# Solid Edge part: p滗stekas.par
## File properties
Author: Andris
Template: Normal.par
Last saved by: Andris
Revision: 4
Application: Solid Edge
Accuracy: 0,990
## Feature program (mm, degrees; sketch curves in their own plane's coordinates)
make body feature "unnamed MakeBodyFeature 1"
thinwall "Thinwall_2"  Thickness = 1 mm
web network "WebNetwork_1"  Thickness = 0.25 mm
sketch for "ExtrudedProtrusion_1" plane through (4.9176, 0.3195, 4.5523) normal (0, 0, 1) x-axis (0, 1, 0)
  line (3.9894, 8.8745) -> (3.9894, 5.5143)
  line (3.9894, 5.5143) -> (-5.3159, 5.5143)
  line (-5.3159, 5.5143) -> (-5.3159, 8.8745)
  line (-5.3159, 8.8745) -> (3.9894, 8.8745)
extrude "ExtrudedProtrusion_1" add finite 2.5924 along +normal
sketch for "ExtrudedProtrusion_2" plane through (4.9176, 0.3195, 4.5523) normal (0, 0, 1) x-axis (0, 1, 0)
  line (-3.765, -4.308) -> (-8.5038, -4.308)
  line (-8.5038, -4.308) -> (-8.5038, -0.4308)
  line (-8.5038, -0.4308) -> (-3.765, -0.4308)
  line (-3.765, -0.4308) -> (-3.765, -4.308)
extrude "ExtrudedProtrusion_2" add finite 2.6405 along +normal
sketch for "ExtrudedProtrusion_3" plane through (4.9176, 0.3195, 4.5523) normal (0, 0, 1) x-axis (0, 1, 0)
  line (-8.7623, -12.9241) -> (7.2635, -12.9241)
  line (7.2635, -12.9241) -> (7.2635, -16.9736)
  line (7.2635, -16.9736) -> (-8.7623, -16.9736)
  line (-8.7623, -16.9736) -> (-8.7623, -12.9241)
extrude "ExtrudedProtrusion_3" add finite 5.2412 along +normal
sketch for "ExtrudedProtrusion_4" plane through (25.184, 0, 6.3726) normal (1, 0, 0) x-axis (0, 1, 0)
  line (8.898, 4.3942) -> (8.898, 2.058)
  line (8.898, 2.058) -> (8.5124, 2.058)
  line (8.5124, 2.058) -> (8.5124, 4.3942)
  line (8.5124, 4.3942) -> (8.898, 4.3942)
extrude "ExtrudedProtrusion_4" add finite 0.5 along +normal
sketch for "ExtrudedProtrusion_5" plane through (25.184, 0, 6.3726) normal (1, 0, 0) x-axis (0, 1, 0)
  line (6.2669, 2.9879) -> (7.1288, 2.0353)
  line (7.1288, 2.0353) -> (7.7866, 2.0353)
  line (7.7866, 2.0353) -> (6.834, 2.9879)
  bspline degree 3 poles (6.7432, 4.3942) (7.7103, 3.9406) (7.7405, 3.4718) (6.834, 2.9879) knots 0 1 multiplicities 4 4
  line (5.5638, 4.3942) -> (6.7432, 4.3942)
  line (5.5638, 4.3942) -> (5.5638, 2.0353)
  line (5.5638, 2.0353) -> (6.2669, 2.0353)
  line (6.2669, 2.0353) -> (6.2669, 2.9879)
extrude "ExtrudedProtrusion_5" add finite 0.5 along +normal
sketch for "ExtrudedProtrusion_7" plane through (25.184, 0, 6.3726) normal (1, 0, 0) x-axis (0, 1, 0)
  line (3.1863, 4.3205) -> (3.1863, 2.5044)
  line (3.1863, 4.3205) -> (2.5601, 4.3205)
  line (2.5601, 4.3205) -> (2.5601, 2.16)
  bspline degree 3 poles (4.7832, 2.16) (4.0838, 1.5934) (3.3428, 1.5934) (2.5601, 2.16) knots 0 1 multiplicities 4 4
  line (4.7832, 4.3205) -> (4.7832, 2.16)
  line (4.7832, 4.3205) -> (4.0944, 4.3205)
  line (4.0944, 4.3205) -> (4.0944, 2.5044)
  arc centre (4.0944, -14.1338) radius 16.6383 from (4.0944, 2.5044) to (3.1863, 2.4796) ccw
extrude "ExtrudedProtrusion_7" add finite 0.5 along +normal
sketch for "ExtrudedProtrusion_8" plane through (25.184, 0, 6.3726) normal (1, 0, 0) x-axis (0, 1, 0)
  line (-0.4881, 4.3205) -> (-0.4881, 2.5044)
  line (-0.4881, 4.3205) -> (-1.1144, 4.3205)
  line (-1.1144, 4.3205) -> (-1.1144, 2.16)
  bspline degree 3 poles (1.1088, 2.16) (0.4094, 1.5934) (-0.3317, 1.5934) (-1.1144, 2.16) knots 0 1 multiplicities 4 4
  line (1.1088, 4.3205) -> (1.1088, 2.16)
  line (1.1088, 4.3205) -> (0.4199, 4.3205)
  line (0.4199, 4.3205) -> (0.4199, 2.5044)
  arc centre (0.4199, -14.1338) radius 16.6383 from (0.4199, 2.5044) to (-0.4881, 2.4796) ccw
extrude "ExtrudedProtrusion_8" add finite 0.5 along +normal
sketch for "ExtrudedProtrusion_9" plane through (25.184, 0, 6.3726) normal (1, 0, 0) x-axis (0, 1, 0)
  line (-2.9192, 3.421) -> (-2.9192, 1.7858)
  line (-2.9192, 1.7858) -> (-3.6904, 1.7858)
  line (-3.6904, 1.7858) -> (-3.6904, 3.421)
  line (-3.6904, 3.421) -> (-4.8472, 3.421)
  line (-4.8472, 3.421) -> (-4.8245, 4.3205)
  line (-4.8245, 4.3205) -> (-1.9439, 4.3205)
  line (-1.9439, 4.3205) -> (-1.9439, 3.421)
  line (-1.9439, 3.421) -> (-2.9192, 3.421)
extrude "ExtrudedProtrusion_9" add finite 0.5 along +normal
sketch for "unnamed Protrusion 1" plane through (25.184, 0, 6.3726) normal (1, 0, 0) x-axis (0, 1, 0)
  line (-6.2575, 4.3205) -> (-6.2575, 2.5044)
  line (-6.2575, 4.3205) -> (-5.6313, 4.3205)
  line (-5.6313, 4.3205) -> (-5.6313, 2.16)
  bspline degree 3 poles (-7.8544, 2.16) (-7.155, 1.5934) (-6.414, 1.5934) (-5.6313, 2.16) knots 0 1 multiplicities 4 4
  line (-7.8544, 4.3205) -> (-7.8544, 2.16)
  line (-7.8544, 4.3205) -> (-7.1656, 4.3205)
  line (-7.1656, 4.3205) -> (-7.1656, 2.5044)
  arc centre (-7.1656, -14.1338) radius 16.6383 from (-7.1656, 2.5044) to (-6.2575, 2.4796) cw
extrude "unnamed Protrusion 1" add finite 0.5 along +normal
sketch for "ExtrudedProtrusion_11" plane through (25.184, 0, 6.3726) normal (1, 0, 0) x-axis (0, 1, 0)
  line (-8.8251, 3.1307) -> (-9.4545, 3.1307)
  line (-9.4545, 3.1307) -> (-9.4545, 3.7882)
  line (-9.4545, 3.7882) -> (-8.4428, 3.7882)
  line (-8.4428, 3.7882) -> (-8.4428, 4.3205)
  line (-8.4428, 4.3205) -> (-10.0776, 4.3205)
  line (-10.0776, 4.3205) -> (-10.0776, 1.9408)
  line (-10.0776, 1.9408) -> (-9.4545, 1.9408)
  line (-9.4545, 1.9408) -> (-9.4545, 2.5984)
  line (-9.4545, 2.5984) -> (-8.8251, 2.5984)
  line (-8.8251, 2.5984) -> (-8.8251, 3.1307)
extrude "ExtrudedProtrusion_11" add finite 0.5 along +normal
sketch for "ExtrudedProtrusion_12" plane through (-4.1931, 0, 0) normal (1, 0, 0) x-axis (0, 1, 0)
  line (16.7769, 11.2976) -> (16.7769, 0)
  line (16.7769, 0) -> (16.7769, -3.4038)
  line (16.7769, -3.4038) -> (-16.763, -3.4038)
  line (-16.763, -3.4038) -> (-16.763, 11.0814)
  line (-16.763, 11.0814) -> (-14.6275, 11.0814)
  bspline degree 3 poles (-14.6275, 11.0814) (-14.5757, 9.0634) (-14.3508, 5.8906) (-9.9977, 2.2169) (-5.2623, -0.108) (-1.6651, -0.5619) (0, -0.7388) knots 0 0.264 0.4468 0.7811 1 multiplicities 4 1 1 1 4
  bspline degree 3 poles (14.6275, 11.0814) (14.5757, 9.0634) (14.3508, 5.8906) (9.9977, 2.2169) (5.2623, -0.108) (1.6651, -0.5619) (0, -0.7388) knots 0 0.264 0.4468 0.7811 1 multiplicities 4 1 1 1 4
  line (14.6275, 11.0814) -> (14.4867, 11.2976)
  line (14.4867, 11.2976) -> (16.7769, 11.2976)
extrude "ExtrudedProtrusion_12" add finite 5 symmetric
mirror "unnamed Mirror 1" of "ExtrudedProtrusion_12" about plane through (4.3884, 0, 0) normal (1, 0, 0)
extrude "unnamed Protrusion 2" add finite 5 symmetric
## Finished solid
Body 1: solid body, 109 faces, 276 edges, 184 vertices, 3 separate solids.
  Faces by surface: plane 92, swept 8, offset 4, cylinder 3, spline 2
  Edges by curve: line 229, spline 17, intersection 16, curve on surface 8, circle 6
Body 2: solid body, 4 faces, 7 edges, 5 vertices.
  Faces by surface: plane 2, spline 2
  Edges by curve: curve on surface 6, spline 1
Bounding box of the edges (mm; curved faces can reach further): 45.439 x 33.540 x 16.149, from (-19.7553, -16.763, -3.4038) to (25.684, 16.7769, 12.7453).
Cylindrical faces by radius (mm): R16.6383 x3
Planar faces by outward normal: +x 14, +y 19, +z 21, -x 8, -y 15, -z 12, oblique 5
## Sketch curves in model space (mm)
line (-4.1931, 16.7769, 11.2976) -> (-4.1931, 16.7769, 0)
line (-4.1931, 16.7769, 0) -> (-4.1931, 16.7769, -3.4038)
line (-4.1931, 16.7769, -3.4038) -> (-4.1931, -16.763, -3.4038)
line (-4.1931, -16.763, -3.4038) -> (-4.1931, -16.763, 11.0814)
line (-4.1931, -16.763, 11.0814) -> (-4.1931, -14.6275, 11.0814)
spline (-4.1931, -14.6275, 11.0814) -> (-4.1931, -9.8346, 2.3914) -> (-4.1931, 0, -0.7388)
spline (-4.1931, 14.6275, 11.0814) -> (-4.1931, 9.8346, 2.3914) -> (-4.1931, 0, -0.7388)
line (-4.1931, 14.6275, 11.0814) -> (-4.1931, 14.4867, 11.2976)
line (-4.1931, 14.4867, 11.2976) -> (-4.1931, 16.7769, 11.2976)
line (25.184, -10.0776, 8.3134) -> (25.184, -9.4545, 8.3134)
line (25.184, -9.4545, 8.3134) -> (25.184, -9.4545, 8.971)
line (25.184, -9.4545, 8.971) -> (25.184, -8.8251, 8.971)
line (25.184, -8.8251, 8.971) -> (25.184, -8.8251, 9.5033)
line (25.184, -8.8251, 9.5033) -> (25.184, -9.4545, 9.5033)
line (25.184, -9.4545, 9.5033) -> (25.184, -9.4545, 10.1608)
line (25.184, -9.4545, 10.1608) -> (25.184, -8.4428, 10.1608)
line (25.184, -8.4428, 10.1608) -> (25.184, -8.4428, 10.6931)
line (25.184, -8.4428, 10.6931) -> (25.184, -10.0776, 10.6931)
line (25.184, -10.0776, 10.6931) -> (25.184, -10.0776, 8.3134)
arc centre (25.184, -7.1656, -7.7612) radius 16.6383 from (25.184, -7.1656, 8.877) through (25.184, -6.7114, 8.8708) to (25.184, -6.2575, 8.8522)
line (25.184, -7.1656, 10.6931) -> (25.184, -7.1656, 8.877)
line (25.184, -6.2575, 10.6931) -> (25.184, -6.2575, 8.877)
line (25.184, -6.2575, 10.6931) -> (25.184, -5.6313, 10.6931)
line (25.184, -5.6313, 10.6931) -> (25.184, -5.6313, 8.5326)
spline (25.184, -7.8544, 8.5326) -> (25.184, -6.7741, 8.1077) -> (25.184, -5.6313, 8.5326)
line (25.184, -7.8544, 10.6931) -> (25.184, -7.8544, 8.5326)
line (25.184, -7.8544, 10.6931) -> (25.184, -7.1656, 10.6931)
line (25.184, -1.9439, 10.6931) -> (25.184, -1.9439, 9.7936)
line (25.184, -1.9439, 9.7936) -> (25.184, -2.9192, 9.7936)
line (25.184, -2.9192, 9.7936) -> (25.184, -2.9192, 8.1584)
line (25.184, -2.9192, 8.1584) -> (25.184, -3.6904, 8.1584)
line (25.184, -3.6904, 8.1584) -> (25.184, -3.6904, 9.7936)
line (25.184, -3.6904, 9.7936) -> (25.184, -4.8471, 9.7936)
line (25.184, -4.8471, 9.7936) -> (25.184, -4.8245, 10.6931)
line (25.184, -4.8245, 10.6931) -> (25.184, -1.9439, 10.6931)
arc centre (25.184, 0.4199, -7.7612) radius 16.6383 from (25.184, 0.4199, 8.877) through (25.184, -0.0343, 8.8708) to (25.184, -0.4881, 8.8522)
line (25.184, 0.4199, 10.6931) -> (25.184, 0.4199, 8.877)
line (25.184, -0.4881, 10.6931) -> (25.184, -0.4881, 8.877)
line (25.184, -0.4881, 10.6931) -> (25.184, -1.1144, 10.6931)
line (25.184, -1.1144, 10.6931) -> (25.184, -1.1144, 8.5326)
spline (25.184, 1.1088, 8.5326) -> (25.184, 0.0284, 8.1077) -> (25.184, -1.1144, 8.5326)
line (25.184, 1.1088, 10.6931) -> (25.184, 1.1088, 8.5326)
line (25.184, 1.1088, 10.6931) -> (25.184, 0.4199, 10.6931)
arc centre (25.184, 4.0944, -7.7612) radius 16.6383 from (25.184, 4.0944, 8.877) through (25.184, 3.6402, 8.8708) to (25.184, 3.1863, 8.8522)
line (25.184, 4.0944, 10.6931) -> (25.184, 4.0944, 8.877)
line (25.184, 3.1863, 10.6931) -> (25.184, 3.1863, 8.877)
line (25.184, 3.1863, 10.6931) -> (25.184, 2.5601, 10.6931)
line (25.184, 2.5601, 10.6931) -> (25.184, 2.5601, 8.5326)
spline (25.184, 4.7832, 8.5326) -> (25.184, 3.7029, 8.1077) -> (25.184, 2.5601, 8.5326)
line (25.184, 4.7832, 10.6931) -> (25.184, 4.7832, 8.5326)
line (25.184, 4.7832, 10.6931) -> (25.184, 4.0944, 10.6931)
line (25.184, 5.5638, 8.4079) -> (25.184, 6.2669, 8.4079)
line (25.184, 6.2669, 8.4079) -> (25.184, 6.2669, 9.3605)
line (25.184, 6.2669, 9.3605) -> (25.184, 7.1288, 8.4079)
line (25.184, 7.1288, 8.4079) -> (25.184, 7.7866, 8.4079)
line (25.184, 7.7866, 8.4079) -> (25.184, 6.834, 9.3605)
spline (25.184, 6.7432, 10.7668) -> (25.184, 7.4912, 10.075) -> (25.184, 6.834, 9.3605)
line (25.184, 5.5638, 10.7668) -> (25.184, 6.7432, 10.7668)
line (25.184, 5.5638, 10.7668) -> (25.184, 5.5638, 8.4079)
spline (25.184, 6.2669, 10.2451) -> (25.184, 6.6981, 9.9779) -> (25.184, 6.2669, 9.7936)
line (25.184, 6.2669, 10.2451) -> (25.184, 6.2669, 9.7936)
line (25.184, 8.898, 10.7668) -> (25.184, 8.898, 8.4306)
line (25.184, 8.898, 8.4306) -> (25.184, 8.5124, 8.4306)
line (25.184, 8.5124, 8.4306) -> (25.184, 8.5124, 10.7668)
line (25.184, 8.5124, 10.7668) -> (25.184, 8.898, 10.7668)
line (17.8416, 7.5831, 4.5523) -> (21.8912, 7.5831, 4.5523)
line (21.8912, 7.5831, 4.5523) -> (21.8912, -8.4428, 4.5523)
line (21.8912, -8.4428, 4.5523) -> (17.8416, -8.4428, 4.5523)
line (17.8416, -8.4428, 4.5523) -> (17.8416, 7.5831, 4.5523)
line (5.3484, -3.4455, 4.5523) -> (9.2256, -3.4455, 4.5523)
line (9.2256, -3.4455, 4.5523) -> (9.2256, -8.1843, 4.5523)
line (9.2256, -8.1843, 4.5523) -> (5.3484, -8.1843, 4.5523)
line (5.3484, -8.1843, 4.5523) -> (5.3484, -3.4455, 4.5523)
line (-3.957, 4.309, 4.5523) -> (-0.5967, 4.309, 4.5523)
line (-0.5967, 4.309, 4.5523) -> (-0.5967, -4.9964, 4.5523)
line (-0.5967, -4.9964, 4.5523) -> (-3.957, -4.9964, 4.5523)
line (-3.957, -4.9964, 4.5523) -> (-3.957, 4.309, 4.5523)
line (-14.3489, -6.3391, 4.4273) -> (-14.3489, 3.723, 4.4273)
spline (25.184, 13.7851, 12.7453) -> (25.184, 9.8698, 3.6126) -> (25.184, 0, -0.0002)
spline (11.6691, 13.7851, 12.7453) -> (11.6691, 9.9509, 3.5622) -> (11.6691, 0, -0.0002)
spline (5.622, 13.7851, 12.7453) -> (5.622, 11.2317, 4.6307) -> (5.622, 0, -0.0002)
spline (-19.7553, 0, 12.7453) -> (-15.8015, 0, 3.1318) -> (-7.2648, 0, 0)
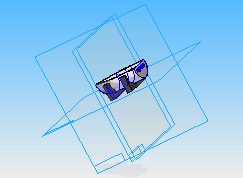
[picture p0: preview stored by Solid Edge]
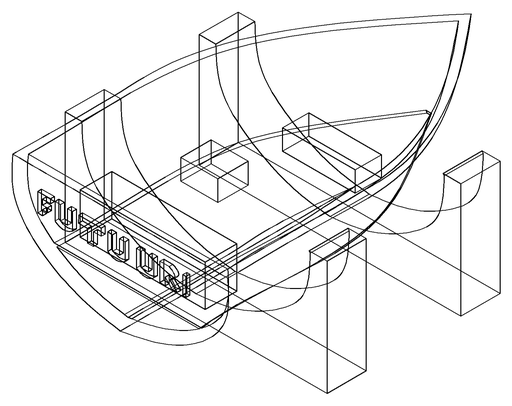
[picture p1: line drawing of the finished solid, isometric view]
